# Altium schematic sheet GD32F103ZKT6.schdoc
size 127 x 101 mm
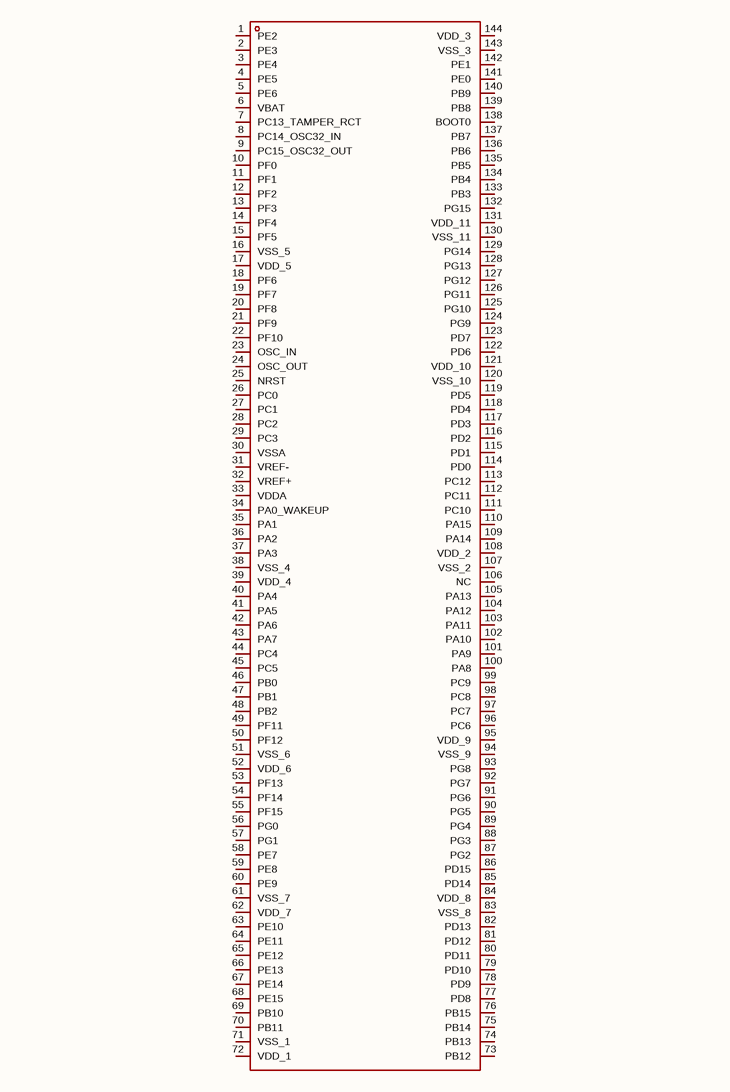
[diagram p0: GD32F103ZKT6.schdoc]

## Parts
U?  gd32f103zkt6  [LQFP-144_L20.0-W20.0-P0.50-LS22.0-BL]  (value not drawn)

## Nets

Not connected (* = marked no-connect by the designer): U? 1(PE2) 2(PE3) 3(PE4) 4(PE5) 5(PE6) 6(VBAT) 7(PC13_TAMPER_RCT) 8(PC14_OSC32_IN) 9(PC15_OSC32_OUT) 10(PF0) 11(PF1) 12(PF2) 13(PF3) 14(PF4) 15(PF5) 16(VSS_5) 17(VDD_5) 18(PF6) 19(PF7) 20(PF8) 21(PF9) 22(PF10) 23(OSC_IN) 24(OSC_OUT) 25(NRST) 26(PC0) 27(PC1) 28(PC2) 29(PC3) 30(VSSA) 31(VREF-) 32(VREF+) 33(VDDA) 34(PA0_WAKEUP) 35(PA1) 36(PA2) 37(PA3) 38(VSS_4) 39(VDD_4) 40(PA4) 41(PA5) 42(PA6) 43(PA7) 44(PC4) 45(PC5) 46(PB0) 47(PB1) 48(PB2) 49(PF11) 50(PF12) 51(VSS_6) 52(VDD_6) 53(PF13) 54(PF14) 55(PF15) 56(PG0) 57(PG1) 58(PE7) 59(PE8) 60(PE9) 61(VSS_7) 62(VDD_7) 63(PE10) 64(PE11) 65(PE12) 66(PE13) 67(PE14) 68(PE15) 69(PB10) 70(PB11) 71(VSS_1) 72(VDD_1) 73(PB12) 74(PB13) 75(PB14) 76(PB15) 77(PD8) 78(PD9) 79(PD10) 80(PD11) 81(PD12) 82(PD13) 83(VSS_8) 84(VDD_8) 85(PD14) 86(PD15) 87(PG2) 88(PG3) 89(PG4) 90(PG5) 91(PG6) 92(PG7) 93(PG8) 94(VSS_9) 95(VDD_9) 96(PC6) 97(PC7) 98(PC8) 99(PC9) 100(PA8) 101(PA9) 102(PA10) 103(PA11) 104(PA12) 105(PA13) 106(NC) 107(VSS_2) 108(VDD_2) 109(PA14) 110(PA15) 111(PC10) 112(PC11) 113(PC12) 114(PD0) 115(PD1) 116(PD2) 117(PD3) 118(PD4) 119(PD5) 120(VSS_10) 121(VDD_10) 122(PD6) 123(PD7) 124(PG9) 125(PG10) 126(PG11) 127(PG12) 128(PG13) 129(PG14) 130(VSS_11) 131(VDD_11) 132(PG15) 133(PB3) 134(PB4) 135(PB5) 136(PB6) 137(PB7) 138(BOOT0) 139(PB8) 140(PB9) 141(PE0) 142(PE1) 143(VSS_3) 144(VDD_3)

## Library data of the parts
U? = gd32f103zkt6: CPU内核:ARM Cortex-M3;CPU最大主频:108MHz;; Manufacturer: GigaDevice(兆易创新); AddInBom: yes; ModelId: 4b55735481674d0c808bacd550892b80; ModelTransform: 866.14,866.14,0,0,0,0,0,0,0; CPU Maximum Speed: 108MHz; Program Storage Size: 3MB; Program Memory Type: FLASH; Number of I/O: 112; ADC (Bit): 12bit; Voltage - Supply: 2.6V~3.6V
